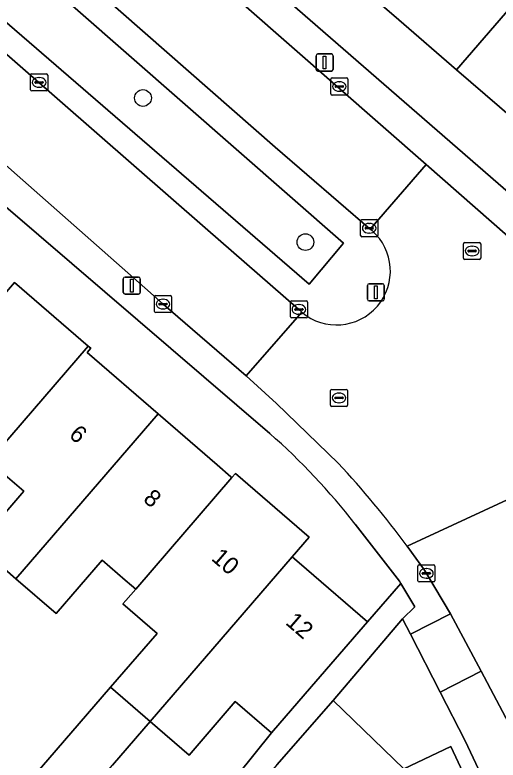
# Model space of a CAD drawing. Extents: x 158352 to 159489, y 383828 to 384603.
# Drawn here: x 159065.04 to 159093.28, y 384024.65 to 384068.15 of the extents above; entities that cross this region are included whole.
import ezdxf

# ---------------------------------------------------------------- set-up
doc = ezdxf.new("R2010")
doc.units = 0
for name, color, linetype in [('IMGEO_Boom', 7, 'Continuous'), ('IMGEO_Erf', 7, 'Continuous'), ('IMGEO_Groenvoorziening', 7, 'Continuous'), ('IMGEO_Kolk', 7, 'Continuous'), ('IMGEO_Lichtmast', 7, 'Continuous'), ('IMGEO_Pand', 7, 'Continuous'), ('IMGEO_Pand_nummerreeks', 7, 'Continuous'), ('IMGEO_Rijbaan_lokaal_gesloten', 7, 'Continuous'), ('IMGEO_Rijbaan_lokaal_open', 7, 'Continuous'), ('IMGEO_Rioolput', 7, 'Continuous'), ('IMGEO_Voetpad_open', 7, 'Continuous')]:
    doc.layers.add(name, color=color, linetype=linetype)

msp = doc.modelspace()

# ---------------------------------------------------------------- linework, layer by layer
at = {"layer": 'IMGEO_Boom'}
for centre in [(159072.528, 384063.3), (159082.018, 384054.885)]:
    msp.add_circle(centre, 0.489, dxfattribs=at)
at = {"layer": 'IMGEO_Erf'}
for points in [[(159075.619, 384073.668), (159096.403, 384055.601), (159099.594, 384052.806), (159101.266, 384051.342), (159101.629, 384050.577), (159102.013, 384050.763), (159110.91, 384055.417), (159110.622, 384055.905), (159116.557, 384059.082), (159126.701, 384064.513), (159129.89, 384066.253)], [(159106.809, 384069.343), (159108.468, 384067.911), (159110.594, 384066.076), (159107.719, 384062.744), (159109.998, 384060.777), (159104.59, 384054.506), (159100.183, 384058.307), (159099.202, 384057.17), (159094.887, 384060.892), (159095.173, 384061.224), (159095.052, 384061.328), (159094.201, 384062.063), (159090.857, 384064.947), (159087.486, 384067.855), (159086.649, 384068.577)], [(159062.569, 384058.605), (159059.659, 384055.212), (159063.103, 384052.237), (159063.996, 384051.466), (159064.056, 384051.415), (159065.025, 384052.536), (159069.33, 384048.817), (159069.481, 384048.686), (159069.269, 384048.44), (159073.422, 384044.852), (159076.866, 384041.877), (159077.671, 384041.182), (159077.727, 384041.134), (159077.935, 384041.375), (159082.24, 384037.657), (159081.251, 384036.513), (159081.389, 384036.394), (159082.088, 384035.79), (159085.647, 384032.716), (159087.586, 384034.96), (159087.508, 384035.087), (159084.924, 384038.424)], [(159079.935, 384043.709), (159062.569, 384058.605)], [(159066.119, 384023.662), (159070.638, 384028.894), (159073.353, 384032.037), (159071.356, 384033.763), (159071.526, 384033.959), (159072.104, 384034.627), (159071.853, 384034.844), (159071.496, 384035.152), (159070.142, 384036.323), (159067.447, 384033.203), (159065.104, 384035.228), (159062.837, 384037.186), (159065.562, 384040.34), (159064.341, 384041.396)], [(159068.125, 384011.403), (159080.042, 384026.228), (159077.922, 384028.06), (159075.222, 384024.935), (159072.945, 384026.902), (159070.745, 384024.356)]]:
    msp.add_lwpolyline(points, dxfattribs=at)
msp.add_lwpolyline([(159089.901, 384028.605), (159088.167, 384031.989), (159087.701, 384032.897), (159083.633, 384028.131), (159087.762, 384024.144), (159090.518, 384025.435), (159093.2, 384019.698), (159095.893, 384013.937), (159098.497, 384008.367), (159101.169, 384002.651), (159102.408, 384000), (159104.007, 383996.579), (159104.119, 383996.631), (159104.187, 383996.487), (159102.431, 383995.664), (159103.195, 383994.033), (159103.84, 383994.336), (159105.742, 383995.228), (159103.494, 384000), (159091.357, 384025.766)], close=True, dxfattribs=at)
msp.add_arc((159054.902, 384015.081), 38.029, 37.8664, 48.833, dxfattribs=at)
at = {"layer": 'IMGEO_Groenvoorziening'}
for points in [[(159050.8, 384086.238), (159049.737, 384085.023), (159084.241, 384054.827), (159082.23, 384052.422), (159047.486, 384082.448), (159046.647, 384081.489), (159076.165, 384055.717), (159081.639, 384050.956), (159081.812, 384050.789)], [(159085.911, 384055.561), (159085.805, 384055.65), (159080.25, 384060.43), (159050.8, 384086.238)]]:
    msp.add_lwpolyline(points, dxfattribs=at)
msp.add_lwpolyline([(159049.737, 384085.023), (159047.486, 384082.448), (159082.23, 384052.422), (159084.241, 384054.827)], close=True, dxfattribs=at)
msp.add_arc((159083.837, 384053.196), 3.146, 229.9353, 48.7416, dxfattribs=at)
at = {"layer": 'IMGEO_Kolk'}
for p, q in [((159065.959, 384063.783), (159065.959, 384064.635)), ((159066.034, 384064.709), (159066.886, 384064.709)), ((159066.447, 384064.489), (159066.472, 384064.489)), ((159066.96, 384064.635), (159066.96, 384063.783)), ((159083.501, 384063.544), (159083.501, 384064.396)), ((159083.576, 384064.47), (159084.428, 384064.47)), ((159084.502, 384064.396), (159084.502, 384063.544)), ((159066.218, 384064.203), (159066.218, 384064.215)), ((159066.656, 384064.166), (159066.258, 384064.166)), ((159066.261, 384064.252), (159066.659, 384064.252)), ((159066.47, 384063.929), (159066.445, 384063.929)), ((159066.702, 384064.215), (159066.702, 384064.203)), ((159083.76, 384063.964), (159083.76, 384063.976)), ((159084.198, 384063.927), (159083.8, 384063.927)), ((159083.803, 384064.013), (159084.201, 384064.013)), ((159083.989, 384064.25), (159084.014, 384064.25)), ((159084.244, 384063.976), (159084.244, 384063.964)), ((159066.886, 384063.709), (159066.034, 384063.709)), ((159084.428, 384063.47), (159083.576, 384063.47)), ((159084.012, 384063.69), (159083.987, 384063.69)), ((159085.246, 384055.271), (159085.246, 384056.123)), ((159085.321, 384056.197), (159086.173, 384056.197)), ((159086.247, 384056.123), (159086.247, 384055.271)), ((159085.505, 384055.691), (159085.505, 384055.703)), ((159085.943, 384055.654), (159085.545, 384055.654)), ((159085.548, 384055.74), (159085.946, 384055.74)), ((159085.734, 384055.977), (159085.759, 384055.977)), ((159085.989, 384055.703), (159085.989, 384055.691)), ((159086.173, 384055.197), (159085.321, 384055.197)), ((159085.757, 384055.417), (159085.732, 384055.417)), ((159073.272, 384051.768), (159074.124, 384051.768)), ((159073.197, 384050.842), (159073.197, 384051.694)), ((159073.456, 384051.262), (159073.456, 384051.274)), ((159073.499, 384051.311), (159073.897, 384051.311)), ((159073.685, 384051.548), (159073.71, 384051.548)), ((159073.94, 384051.274), (159073.94, 384051.262)), ((159074.198, 384051.694), (159074.198, 384050.842)), ((159081.139, 384050.531), (159081.139, 384051.383)), ((159081.214, 384051.457), (159082.066, 384051.457)), ((159082.14, 384051.383), (159082.14, 384050.531)), ((159073.894, 384051.225), (159073.496, 384051.225)), ((159073.708, 384050.988), (159073.683, 384050.988)), ((159081.398, 384050.951), (159081.398, 384050.963)), ((159081.836, 384050.914), (159081.438, 384050.914)), ((159081.441, 384051), (159081.839, 384051)), ((159081.627, 384051.237), (159081.652, 384051.237)), ((159081.882, 384050.963), (159081.882, 384050.951)), ((159074.124, 384050.768), (159073.272, 384050.768)), ((159082.066, 384050.457), (159081.214, 384050.457)), ((159081.65, 384050.677), (159081.625, 384050.677)), ((159088.662, 384036.046), (159089.514, 384036.046)), ((159088.587, 384035.12), (159088.587, 384035.972)), ((159089.075, 384035.826), (159089.1, 384035.826)), ((159089.588, 384035.972), (159089.588, 384035.12)), ((159088.846, 384035.54), (159088.846, 384035.552)), ((159089.284, 384035.503), (159088.886, 384035.503)), ((159088.889, 384035.589), (159089.287, 384035.589)), ((159089.098, 384035.266), (159089.073, 384035.266)), ((159089.33, 384035.552), (159089.33, 384035.54)), ((159089.514, 384035.046), (159088.662, 384035.046))]:
    msp.add_line(p, q, dxfattribs=at)
for points in [[(159065.959, 384063.783), (159065.959, 384064.635)], [(159066.034, 384064.709), (159066.886, 384064.709)], [(159066.96, 384064.635), (159066.96, 384063.783)], [(159083.501, 384063.544), (159083.501, 384064.396)], [(159083.576, 384064.47), (159084.428, 384064.47)], [(159084.502, 384064.396), (159084.502, 384063.544)], [(159066.886, 384063.709), (159066.034, 384063.709)], [(159084.428, 384063.47), (159083.576, 384063.47)], [(159085.246, 384055.271), (159085.246, 384056.123)], [(159085.321, 384056.197), (159086.173, 384056.197)], [(159086.247, 384056.123), (159086.247, 384055.271)], [(159086.173, 384055.197), (159085.321, 384055.197)], [(159073.272, 384051.768), (159074.124, 384051.768)], [(159073.197, 384050.842), (159073.197, 384051.694)], [(159074.198, 384051.694), (159074.198, 384050.842)], [(159081.139, 384050.531), (159081.139, 384051.383)], [(159081.214, 384051.457), (159082.066, 384051.457)], [(159082.14, 384051.383), (159082.14, 384050.531)], [(159074.124, 384050.768), (159073.272, 384050.768)], [(159082.066, 384050.457), (159081.214, 384050.457)], [(159088.662, 384036.046), (159089.514, 384036.046)], [(159088.587, 384035.12), (159088.587, 384035.972)], [(159089.588, 384035.972), (159089.588, 384035.12)], [(159089.514, 384035.046), (159088.662, 384035.046)]]:
    msp.add_lwpolyline(points, dxfattribs=at)
for centre, radius, start, end in [((159066.036, 384064.633), 0.0765, 91.552, 178.448), ((159066.036, 384064.633), 0.0765, 91.552, 178.448), ((159066.884, 384064.633), 0.0765, 1.552, 88.448), ((159066.884, 384064.633), 0.0765, 1.552, 88.448), ((159083.578, 384064.394), 0.0765, 91.552, 178.448), ((159083.578, 384064.394), 0.0765, 91.552, 178.448), ((159084.426, 384064.394), 0.0765, 1.552, 88.448), ((159084.426, 384064.394), 0.0765, 1.552, 88.448), ((159066.258, 384064.212), 0.0403, 85.8775, 175.7526), ((159066.255, 384064.202), 0.0366, 178.938, 274.7102), ((159066.659, 384064.209), 0.043, 264.8664, 352.4533), ((159066.663, 384064.214), 0.0386, 1.7309, 96.639), ((159083.8, 384063.973), 0.0403, 85.8775, 175.7526), ((159083.797, 384063.963), 0.0366, 178.938, 274.7102), ((159084.201, 384063.97), 0.043, 264.8664, 352.4533), ((159084.205, 384063.975), 0.0386, 1.7309, 96.639), ((159066.036, 384063.785), 0.0765, 181.552, 268.448), ((159066.036, 384063.785), 0.0765, 181.552, 268.448), ((159066.884, 384063.785), 0.0765, 271.552, 358.448), ((159066.884, 384063.785), 0.0765, 271.552, 358.448), ((159083.578, 384063.546), 0.0765, 181.552, 268.448), ((159083.578, 384063.546), 0.0765, 181.552, 268.448), ((159084.426, 384063.546), 0.0765, 271.552, 358.448), ((159084.426, 384063.546), 0.0765, 271.552, 358.448), ((159085.323, 384056.121), 0.0765, 91.552, 178.448), ((159085.323, 384056.121), 0.0765, 91.552, 178.448), ((159086.171, 384056.121), 0.0765, 1.552, 88.448), ((159086.171, 384056.121), 0.0765, 1.552, 88.448), ((159085.545, 384055.7), 0.0403, 85.8775, 175.7526), ((159085.542, 384055.69), 0.0366, 178.938, 274.7102), ((159085.946, 384055.697), 0.043, 264.8664, 352.4533), ((159085.95, 384055.702), 0.0386, 1.7309, 96.639), ((159085.323, 384055.273), 0.0765, 181.552, 268.448), ((159085.323, 384055.273), 0.0765, 181.552, 268.448), ((159086.171, 384055.273), 0.0765, 271.552, 358.448), ((159086.171, 384055.273), 0.0765, 271.552, 358.448), ((159073.274, 384051.692), 0.0765, 91.552, 178.448), ((159073.274, 384051.692), 0.0765, 91.552, 178.448), ((159074.122, 384051.692), 0.0765, 1.552, 88.448), ((159074.122, 384051.692), 0.0765, 1.552, 88.448), ((159073.496, 384051.271), 0.0403, 85.8775, 175.7526), ((159073.901, 384051.273), 0.0386, 1.7309, 96.639), ((159081.216, 384051.381), 0.0765, 91.552, 178.448), ((159081.216, 384051.381), 0.0765, 91.552, 178.448), ((159082.064, 384051.381), 0.0765, 1.552, 88.448), ((159082.064, 384051.381), 0.0765, 1.552, 88.448), ((159073.274, 384050.844), 0.0765, 181.552, 268.448), ((159073.274, 384050.844), 0.0765, 181.552, 268.448), ((159073.493, 384051.261), 0.0366, 178.938, 274.7102), ((159073.897, 384051.268), 0.043, 264.8664, 352.4533), ((159074.122, 384050.844), 0.0765, 271.552, 358.448), ((159074.122, 384050.844), 0.0765, 271.552, 358.448), ((159081.438, 384050.96), 0.0403, 85.8775, 175.7526), ((159081.435, 384050.95), 0.0366, 178.938, 274.7102), ((159081.839, 384050.957), 0.043, 264.8664, 352.4533), ((159081.843, 384050.962), 0.0386, 1.7309, 96.639), ((159081.216, 384050.533), 0.0765, 181.552, 268.448), ((159081.216, 384050.533), 0.0765, 181.552, 268.448), ((159082.064, 384050.533), 0.0765, 271.552, 358.448), ((159082.064, 384050.533), 0.0765, 271.552, 358.448), ((159088.664, 384035.97), 0.0765, 91.552, 178.448), ((159088.664, 384035.97), 0.0765, 91.552, 178.448), ((159089.512, 384035.97), 0.0765, 1.552, 88.448), ((159089.512, 384035.97), 0.0765, 1.552, 88.448), ((159088.886, 384035.549), 0.0403, 85.8775, 175.7526), ((159088.883, 384035.539), 0.0366, 178.938, 274.7102), ((159089.287, 384035.546), 0.043, 264.8664, 352.4533), ((159089.291, 384035.551), 0.0386, 1.7309, 96.639), ((159088.664, 384035.122), 0.0765, 181.552, 268.448), ((159088.664, 384035.122), 0.0765, 181.552, 268.448), ((159089.512, 384035.122), 0.0765, 271.552, 358.448), ((159089.512, 384035.122), 0.0765, 271.552, 358.448)]:
    msp.add_arc(centre, radius, start, end, dxfattribs=at)
for centre, major_axis, ratio, start_param, end_param in [((159066.446, 384064.209), (-0.387, 0.002), 0.722429, 4.712389, 7.853982), ((159066.471, 384064.209), (-0.39, 0.002), 0.717154, 1.570796, 4.712389), ((159083.988, 384063.97), (-0.387, 0.002), 0.722429, 4.712389, 7.853982), ((159084.013, 384063.97), (-0.39, 0.002), 0.717154, 1.570796, 4.712389), ((159085.733, 384055.697), (-0.387, 0.002), 0.722429, 4.712389, 7.853982), ((159085.758, 384055.697), (-0.39, 0.002), 0.717154, 1.570796, 4.712389), ((159073.684, 384051.268), (-0.387, 0.002), 0.722429, 4.712389, 7.853982), ((159073.709, 384051.268), (-0.39, 0.002), 0.717154, 1.570796, 4.712389), ((159081.626, 384050.957), (-0.387, 0.002), 0.722429, 4.712389, 7.853982), ((159081.651, 384050.957), (-0.39, 0.002), 0.717154, 1.570796, 4.712389), ((159089.074, 384035.546), (-0.387, 0.002), 0.722429, 4.712389, 7.853982), ((159089.099, 384035.546), (-0.39, 0.002), 0.717154, 1.570796, 4.712389)]:
    msp.add_ellipse(centre, major_axis=major_axis, ratio=ratio, start_param=start_param, end_param=end_param, dxfattribs=at)
at = {"layer": 'IMGEO_Lichtmast'}
for p, q in [((159082.645, 384064.969), (159082.645, 384065.769)), ((159082.645, 384065.769), (159082.645, 384064.969)), ((159082.745, 384065.869), (159083.535, 384065.869)), ((159083.535, 384065.869), (159082.745, 384065.869)), ((159083.635, 384065.769), (159083.635, 384064.969)), ((159083.635, 384064.969), (159083.635, 384065.769)), ((159083.535, 384064.869), (159082.745, 384064.869)), ((159082.745, 384064.869), (159083.535, 384064.869)), ((159071.378, 384051.948), (159071.378, 384052.748)), ((159071.378, 384052.748), (159071.378, 384051.948)), ((159071.478, 384052.848), (159072.268, 384052.848)), ((159072.268, 384052.848), (159071.478, 384052.848)), ((159072.368, 384052.748), (159072.368, 384051.948)), ((159072.368, 384051.948), (159072.368, 384052.748)), ((159085.64, 384051.554), (159085.64, 384052.354)), ((159085.64, 384052.354), (159085.64, 384051.554)), ((159085.74, 384052.454), (159086.53, 384052.454)), ((159086.53, 384052.454), (159085.74, 384052.454)), ((159086.63, 384052.354), (159086.63, 384051.554)), ((159086.63, 384051.554), (159086.63, 384052.354)), ((159072.268, 384051.848), (159071.478, 384051.848)), ((159071.478, 384051.848), (159072.268, 384051.848)), ((159086.53, 384051.454), (159085.74, 384051.454)), ((159085.74, 384051.454), (159086.53, 384051.454))]:
    msp.add_line(p, q, dxfattribs=at)
for points in [[(159083.065, 384065.744), (159083.215, 384065.744), (159083.215, 384064.994), (159083.065, 384064.994), (159083.065, 384065.744)], [(159071.798, 384052.723), (159071.948, 384052.723), (159071.948, 384051.973), (159071.798, 384051.973), (159071.798, 384052.723)], [(159086.06, 384052.329), (159086.21, 384052.329), (159086.21, 384051.579), (159086.06, 384051.579), (159086.06, 384052.329)]]:
    msp.add_lwpolyline(points, dxfattribs=at)
for centre, start, end in [((159082.745, 384065.769), 90, 180), ((159082.745, 384065.769), 90, 180), ((159083.535, 384065.769), 0, 90), ((159083.535, 384065.769), 360, 90), ((159082.745, 384064.969), 180, 270), ((159082.745, 384064.969), 180, 270), ((159083.535, 384064.969), 270, 0), ((159083.535, 384064.969), 270, 0), ((159071.478, 384052.748), 90, 180), ((159071.478, 384052.748), 90, 180), ((159072.268, 384052.748), 0, 90), ((159072.268, 384052.748), 360, 90), ((159085.74, 384052.354), 90, 180), ((159085.74, 384052.354), 90, 180), ((159086.53, 384052.354), 0, 90), ((159086.53, 384052.354), 360, 90), ((159071.478, 384051.948), 180, 270), ((159071.478, 384051.948), 180, 270), ((159072.268, 384051.948), 270, 0), ((159072.268, 384051.948), 270, 0), ((159085.74, 384051.554), 180, 270), ((159085.74, 384051.554), 180, 270), ((159086.53, 384051.554), 270, 0), ((159086.53, 384051.554), 270, 0)]:
    msp.add_arc(centre, 0.1, start, end, dxfattribs=at)
at = {"layer": 'IMGEO_Pand'}
for points in [[(159099.284, 384074.718), (159096.937, 384076.742), (159094.155, 384073.517), (159092.868, 384074.627), (159092.54, 384074.91), (159092.187, 384075.214), (159086.542, 384068.669), (159086.649, 384068.577), (159087.486, 384067.855), (159090.857, 384064.947), (159099.175, 384074.591)], [(159100.817, 384067.767), (159100.535, 384068.01), (159098.72, 384069.575), (159101.505, 384072.802), (159099.284, 384074.718), (159099.175, 384074.591), (159090.857, 384064.947), (159094.201, 384062.063), (159095.052, 384061.328), (159095.173, 384061.224)], [(159069.33, 384048.817), (159065.025, 384052.536), (159064.056, 384051.415), (159055.712, 384041.761), (159058.101, 384039.697), (159059.876, 384038.164), (159062.616, 384041.337), (159062.758, 384041.214), (159063.525, 384042.101)], [(159073.422, 384044.852), (159069.269, 384048.44), (159069.481, 384048.686), (159069.33, 384048.817), (159063.525, 384042.101), (159063.876, 384041.797), (159064.341, 384041.396), (159065.562, 384040.34), (159062.837, 384037.186), (159065.104, 384035.228)], [(159077.727, 384041.134), (159077.671, 384041.182), (159076.866, 384041.877), (159073.422, 384044.852), (159065.104, 384035.228), (159067.447, 384033.203), (159070.142, 384036.323), (159071.496, 384035.152), (159071.853, 384034.844), (159072.104, 384034.627)], [(159081.251, 384036.513), (159082.24, 384037.657), (159077.935, 384041.375), (159077.727, 384041.134), (159072.104, 384034.627), (159071.526, 384033.959), (159071.356, 384033.763), (159073.353, 384032.037), (159070.638, 384028.894), (159072.945, 384026.902)], [(159081.251, 384036.513), (159072.945, 384026.902), (159075.222, 384024.935), (159077.922, 384028.06), (159080.042, 384026.228), (159082.379, 384028.933), (159085.647, 384032.716), (159082.088, 384035.79), (159081.389, 384036.394)], [(159070.745, 384024.356), (159072.945, 384026.902), (159070.638, 384028.894), (159066.119, 384023.662), (159065.721, 384024.006), (159058.449, 384015.464), (159061.203, 384013.667), (159068.249, 384021.821), (159068.424, 384021.67)], [(159093.2, 384019.698), (159090.518, 384025.435), (159087.762, 384024.144), (159083.633, 384028.131), (159080.349, 384024.361), (159079.746, 384023.669), (159077.843, 384021.484), (159078.755, 384019.534), (159080.437, 384020.307), (159082.966, 384014.905)]]:
    msp.add_lwpolyline(points, close=True, dxfattribs=at)
at = {"layer": 'IMGEO_Rijbaan_lokaal_gesloten'}
msp.add_lwpolyline([(159128.468, 383972.902), (159120.969, 383988.562), (159118.981, 383992.691), (159115.546, 383999.845), (159115.473, 384000), (159113.408, 384004.39), (159105.396, 384021.074), (159095.918, 384040.821), (159087.97, 384037.13), (159088.972, 384035.732), (159089.089, 384035.547), (159090.491, 384033.18), (159092.289, 384029.829), (159094.975, 384024.761), (159105.793, 384002.367), (159106.293, 384001.308), (159106.856, 384000), (159107.692, 383998.149), (159108.445, 383996.555), (159111.083, 383990.972), (159113.209, 383986.675), (159114.367, 383984.335), (159118.479, 383975.731), (159121.286, 383969.447)], dxfattribs=at)
at = {"layer": 'IMGEO_Rijbaan_lokaal_open'}
for points in [[(159049.223, 384087.62), (159049.651, 384087.245), (159050.8, 384086.238), (159080.25, 384060.43), (159085.805, 384055.65), (159089.071, 384059.415), (159073.221, 384073.303), (159070.333, 384075.803), (159055.21, 384088.896)], [(159044.502, 384076.915), (159059.85, 384063.435), (159062.325, 384061.286), (159072.969, 384051.921), (159073.699, 384051.269), (159078.554, 384047.077), (159081.812, 384050.789), (159081.639, 384050.956), (159076.165, 384055.717), (159046.647, 384081.489)], [(159096.892, 384049.749), (159098.324, 384051.355), (159093.849, 384055.229), (159089.071, 384059.415), (159085.805, 384055.65), (159085.911, 384055.561)], [(159081.812, 384050.789), (159078.554, 384047.077), (159080.334, 384045.459), (159083.942, 384041.98)], [(159087.97, 384037.13), (159095.918, 384040.821), (159095.551, 384041.586)]]:
    msp.add_lwpolyline(points, dxfattribs=at)
for centre, radius, start, end in [((159083.837, 384053.196), 3.146, 229.9353, 48.7416), ((159040.759, 384002.018), 58.837, 36.63898, 42.78133)]:
    msp.add_arc(centre, radius, start, end, dxfattribs=at)
at = {"layer": 'IMGEO_Rioolput'}
for p, q in [((159091.261, 384053.943), (159091.261, 384054.795)), ((159091.336, 384054.869), (159092.188, 384054.869)), ((159092.262, 384054.795), (159092.262, 384053.943)), ((159091.52, 384054.363), (159091.52, 384054.375)), ((159091.958, 384054.326), (159091.56, 384054.326)), ((159091.563, 384054.412), (159091.961, 384054.412)), ((159091.749, 384054.649), (159091.774, 384054.649)), ((159092.004, 384054.375), (159092.004, 384054.363)), ((159091.772, 384054.089), (159091.747, 384054.089)), ((159092.188, 384053.869), (159091.336, 384053.869)), ((159083.482, 384045.364), (159083.482, 384046.216)), ((159083.557, 384046.29), (159084.409, 384046.29)), ((159083.97, 384046.07), (159083.995, 384046.07)), ((159084.483, 384046.216), (159084.483, 384045.364)), ((159083.741, 384045.784), (159083.741, 384045.796)), ((159084.179, 384045.747), (159083.781, 384045.747)), ((159083.784, 384045.833), (159084.182, 384045.833)), ((159084.225, 384045.796), (159084.225, 384045.784)), ((159084.409, 384045.29), (159083.557, 384045.29)), ((159083.993, 384045.51), (159083.968, 384045.51))]:
    msp.add_line(p, q, dxfattribs=at)
for points in [[(159091.261, 384053.943), (159091.261, 384054.795)], [(159091.336, 384054.869), (159092.188, 384054.869)], [(159092.262, 384054.795), (159092.262, 384053.943)], [(159092.188, 384053.869), (159091.336, 384053.869)], [(159083.482, 384045.364), (159083.482, 384046.216)], [(159083.557, 384046.29), (159084.409, 384046.29)], [(159084.483, 384046.216), (159084.483, 384045.364)], [(159084.409, 384045.29), (159083.557, 384045.29)]]:
    msp.add_lwpolyline(points, dxfattribs=at)
for centre, radius, start, end in [((159091.338, 384054.793), 0.0765, 91.552, 178.448), ((159091.338, 384054.793), 0.0765, 91.552, 178.448), ((159092.186, 384054.793), 0.0765, 1.552, 88.448), ((159092.186, 384054.793), 0.0765, 1.552, 88.448), ((159091.56, 384054.372), 0.0403, 85.8775, 175.7526), ((159091.557, 384054.362), 0.0366, 178.938, 274.7102), ((159091.961, 384054.369), 0.043, 264.8664, 352.4533), ((159091.965, 384054.374), 0.0386, 1.7309, 96.639), ((159091.338, 384053.945), 0.0765, 181.552, 268.448), ((159091.338, 384053.945), 0.0765, 181.552, 268.448), ((159092.186, 384053.945), 0.0765, 271.552, 358.448), ((159092.186, 384053.945), 0.0765, 271.552, 358.448), ((159083.559, 384046.214), 0.0765, 91.552, 178.448), ((159083.559, 384046.214), 0.0765, 91.552, 178.448), ((159084.407, 384046.214), 0.0765, 1.552, 88.448), ((159084.407, 384046.214), 0.0765, 1.552, 88.448), ((159083.781, 384045.793), 0.0403, 85.8775, 175.7526), ((159083.778, 384045.783), 0.0366, 178.938, 274.7102), ((159084.182, 384045.79), 0.043, 264.8664, 352.4533), ((159084.186, 384045.795), 0.0386, 1.7309, 96.639), ((159083.559, 384045.366), 0.0765, 181.552, 268.448), ((159083.559, 384045.366), 0.0765, 181.552, 268.448), ((159084.407, 384045.366), 0.0765, 271.552, 358.448), ((159084.407, 384045.366), 0.0765, 271.552, 358.448)]:
    msp.add_arc(centre, radius, start, end, dxfattribs=at)
for centre, major_axis, ratio, start_param, end_param in [((159091.748, 384054.369), (-0.387, 0.002), 0.722429, 4.712389, 7.853982), ((159091.773, 384054.369), (-0.39, 0.002), 0.717154, 1.570796, 4.712389), ((159083.969, 384045.79), (-0.387, 0.002), 0.722429, 4.712389, 7.853982), ((159083.994, 384045.79), (-0.39, 0.002), 0.717154, 1.570796, 4.712389)]:
    msp.add_ellipse(centre, major_axis=major_axis, ratio=ratio, start_param=start_param, end_param=end_param, dxfattribs=at)
at = {"layer": 'IMGEO_Voetpad_open'}
for points in [[(159075.619, 384073.668), (159074.609, 384074.546), (159055.048, 384091.549), (159054.182, 384089.791), (159055.21, 384088.896), (159070.333, 384075.803), (159073.221, 384073.303), (159089.071, 384059.415), (159093.849, 384055.229), (159098.324, 384051.355), (159099.594, 384052.806), (159096.403, 384055.601)], [(159089.901, 384028.605), (159092.289, 384029.829), (159090.491, 384033.18), (159088.167, 384031.989)]]:
    msp.add_lwpolyline(points, close=True, dxfattribs=at)
for points in [[(159041.502, 384078.446), (159041.89, 384076.342), (159061.297, 384059.696), (159062.569, 384058.605), (159079.935, 384043.709)], [(159083.942, 384041.98), (159080.334, 384045.459), (159078.554, 384047.077), (159073.699, 384051.269), (159072.969, 384051.921), (159062.325, 384061.286), (159061.643, 384060.501), (159059.168, 384062.65), (159059.85, 384063.435), (159044.502, 384076.915)], [(159084.924, 384038.424), (159087.508, 384035.087), (159087.586, 384034.96), (159088.42, 384033.598), (159087.701, 384032.897), (159088.167, 384031.989), (159090.491, 384033.18), (159089.089, 384035.547), (159088.972, 384035.732), (159087.97, 384037.13)], [(159080.349, 384024.361), (159083.633, 384028.131), (159087.701, 384032.897), (159088.42, 384033.598), (159087.586, 384034.96), (159085.647, 384032.716), (159082.379, 384028.933), (159080.042, 384026.228), (159068.125, 384011.403)], [(159114.367, 383984.335), (159113.209, 383986.675), (159112.272, 383986.223), (159107.508, 383996.103), (159108.445, 383996.555), (159107.692, 383998.149), (159106.856, 384000), (159106.293, 384001.308), (159105.793, 384002.367), (159094.975, 384024.761), (159092.289, 384029.829), (159089.901, 384028.605), (159091.357, 384025.766), (159103.494, 384000), (159105.742, 383995.228), (159103.84, 383994.336), (159105.907, 383989.923), (159107.077, 383987.424), (159108.284, 383984.848), (159109.173, 383985.415), (159111.239, 383981.094), (159112.786, 383977.856), (159114.689, 383973.875), (159118.298, 383966.268)]]:
    msp.add_lwpolyline(points, dxfattribs=at)
for centre, radius, start, end in [((159054.902, 384015.081), 38.029, 37.8664, 48.833), ((159040.759, 384002.018), 58.837, 36.63898, 42.78133)]:
    msp.add_arc(centre, radius, start, end, dxfattribs=at)

# ---------------------------------------------------------------- texts
at = {"layer": 'IMGEO_Pand_nummerreeks'}
for s, p in [('6', (159068.146, 384043.548)), ('8', (159072.484, 384039.801)), ('10', (159076.47, 384036.358)), ('12', (159080.801, 384032.617))]:
    msp.add_text(s, height=1, rotation=319.1825, dxfattribs=at).set_placement(p)

doc.saveas('drawing.dxf')
